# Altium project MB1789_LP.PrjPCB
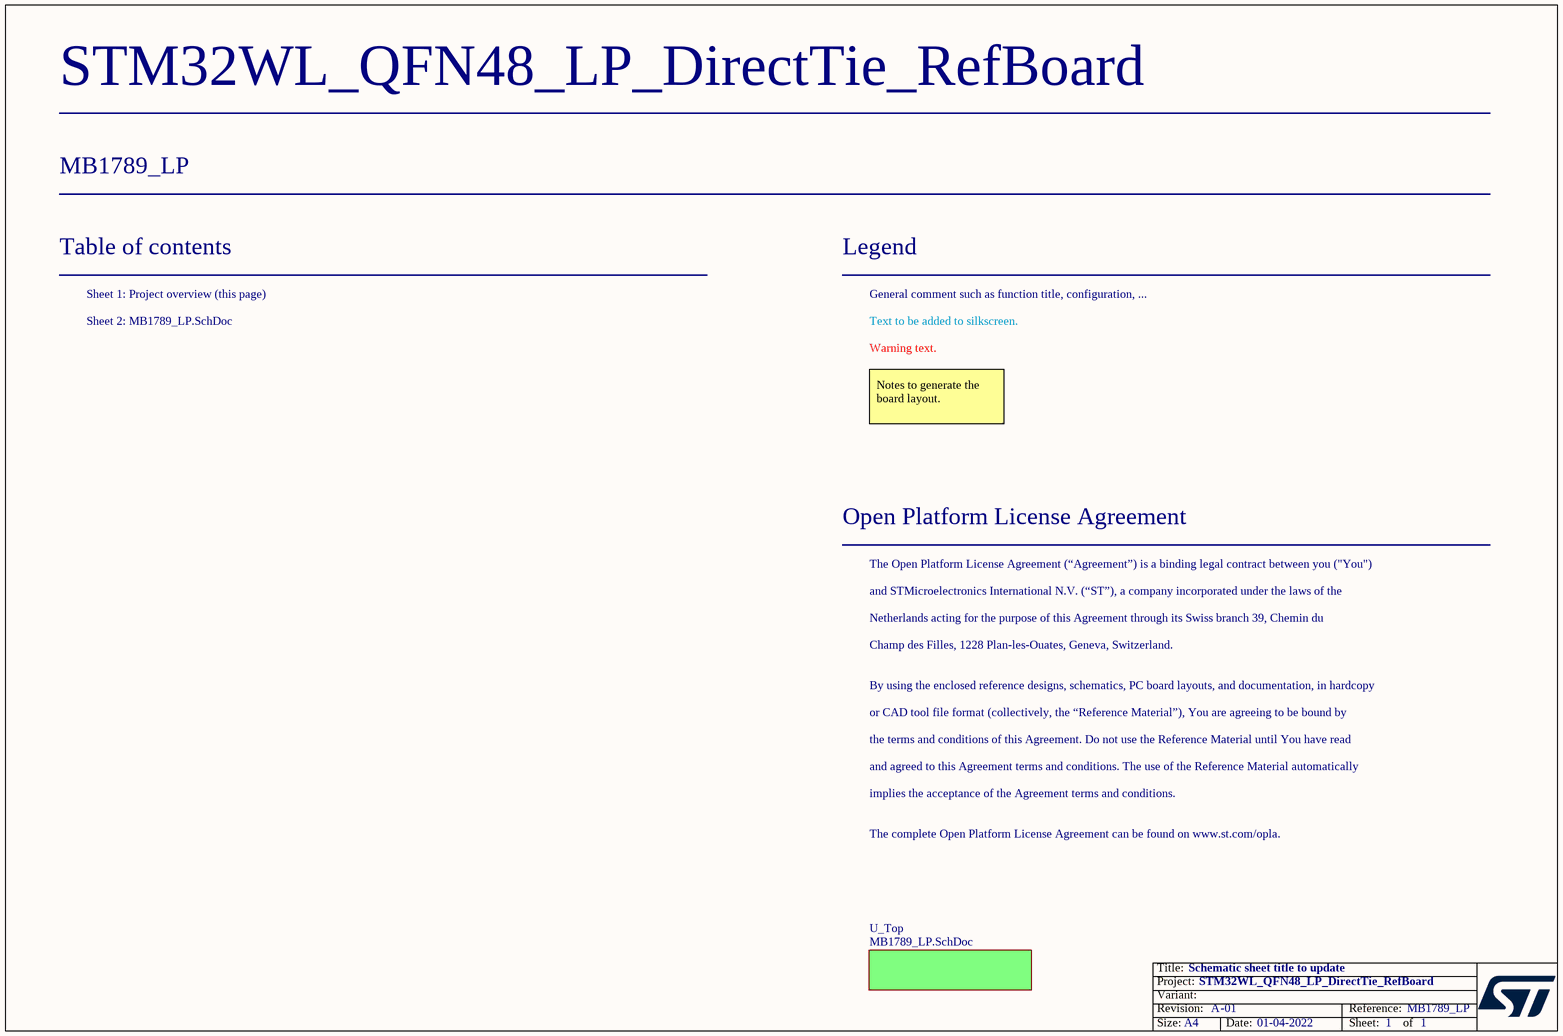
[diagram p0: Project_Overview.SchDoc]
Board_Reference: MB1789_LP; Board_PCB_Revision: A; Board_Name: STM32WL_QFN48_LP_DirectTie_RefBoard; Board_Document_Date: 01-04-2022; Board_Assembly_Revision: 01
2 sheets, 60 parts. Net scope: flat (ports and power ports of the same name join across sheets).
Board file: MB1789_LP.PcbDoc
Sheets:
  Project_Overview.SchDoc
    U_Top = MB1789_LP.SchDoc

## Sheet Project_Overview.SchDoc: Schematic sheet title to update
size A4; Date: Not used; ApprovedBy: Not used; CheckedBy: Not used; Author: Not used; CompanyName: STMicroelectronics; DrawnBy: Not used; Engineer: Not used; Organization: Not used; Address1: Not used; Address2: Not used; Address3: Not used; Address4: Not used; DocumentNumber: Not used; Revision: Not used; SheetNumber: 1; SheetTotal: 1

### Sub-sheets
U_Top = MB1789_LP.SchDoc: no entries

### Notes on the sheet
- Table of contents
- Sheet 1: Project overview (this page)
- Legend
- General comment such as function title, configuration, ...
- Sheet 2: MB1789_LP.SchDoc
- Text to be added to silkscreen.
- Warning text.
- Notes to generate the board layout.
- Open Platform License Agreement
- The Open Platform License Agreement (“Agreement”) is a binding legal contract between you ("You")
- and STMicroelectronics International N.V. (“ST”), a company incorporated under the laws of the
- Netherlands acting for the purpose of this Agreement through its Swiss branch 39, Chemin du
- Champ des Filles, 1228 Plan-les-Ouates, Geneva, Switzerland.
- By using the enclosed reference designs, schematics, PC board layouts, and documentation, in hardcopy
- or CAD tool file format (collectively, the “Reference Material”), You are agreeing to be bound by
- the terms and conditions of this Agreement. Do not use the Reference Material until You have read
- and agreed to this Agreement terms and conditions. The use of the Reference Material automatically
- implies the acceptance of the Agreement terms and conditions.
- The complete Open Platform License Agreement can be found on www.st.com/opla.

## Sheet MB1789_LP.SchDoc: Schematic sheet title to update
size A3; Date: Not used; ApprovedBy: Not used; CheckedBy: Not used; Author: Not used; CompanyName: STMicroelectronics; DrawnBy: Not used; Engineer: Not used; Organization: Not used; Address1: Not used; Address2: Not used; Address3: Not used; Address4: Not used; DocumentNumber: Not used; Revision: Not used; SheetNumber: 1; SheetTotal: 1
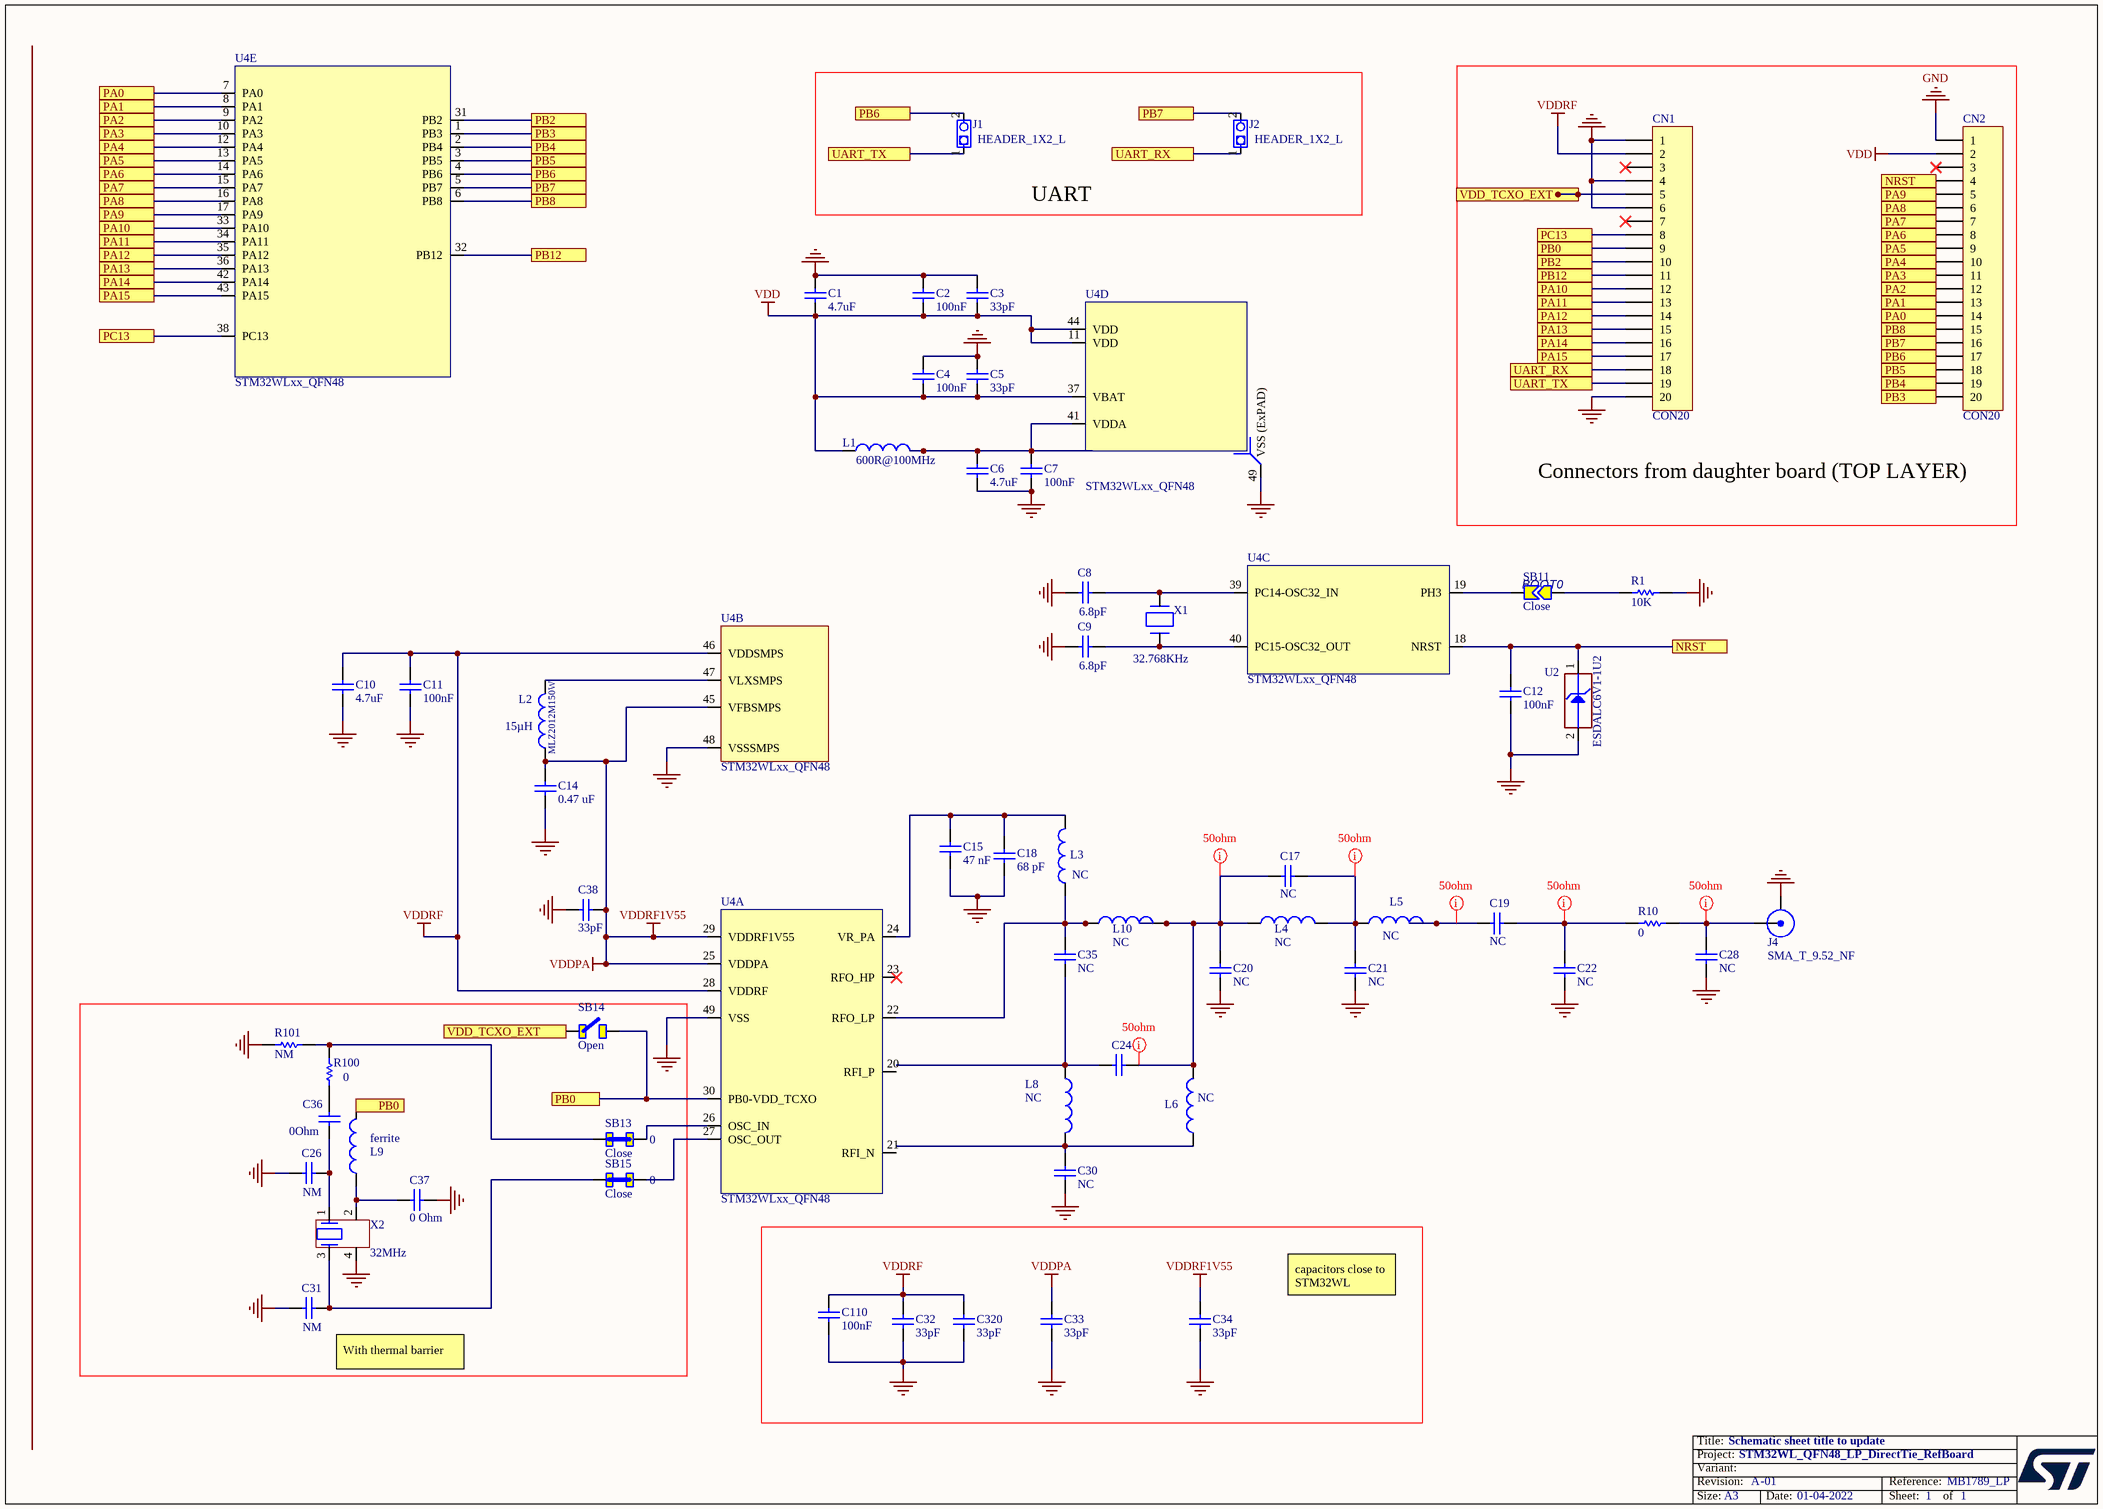
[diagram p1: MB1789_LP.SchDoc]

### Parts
C1  value 4.7uF  [CAPC1608X09N]
C2  value 100nF  [0402]
C3  value 33pF  [0201]
C4  value 100nF  [0402]
C5  value 33pF  [0201]
C6  value 4.7uF  [CAPC1608X09N]
C7  value 100nF  [0402]
C8  value 6.8pF  [0402]  (hidden comment: Capacitor)
C9  value 6.8pF  [0402]  (hidden comment: Capacitor)
C10  value 4.7uF  [CAPC1608X09N]
C11  value 100nF  [0402]
C12  value 100nF  [0402]
C14  value 0.47 uF  [CAPC1608X09N]
C15  value 47 nF  [0402]
C17  value NC  [0402]
C18  value 68 pF  [0402]
C19  value NC  [0402]
C20  value NC  [0402]
C21  value NC  [0402]
C22  value NC  [0402]
C24  (no value)  [0402]
C26  value NM  [0402]  (hidden comment: Capacitor)
C28  value NC  [0402]
C30  value NC  [0402]
C31  value NM  [0402]  (hidden comment: Capacitor)
C32  value 33pF  [0201]
C33  value 33pF  [0201]
C34  value 33pF  [0201]
C35  value NC  [0402]
C36  value 0Ohm  [0402]
C37  value 0 Ohm  [0402]
C38  value 33pF  [0201]
C110  value 100nF  [0402]
C320  value 33pF  [0201]
CN1  CON20
CN2  CON20
J1  HEADER_1X2_L  [CO_MOLEX_22-03-2021]
J2  HEADER_1X2_L  [CO_MOLEX_22-03-2021]
J4  SMA_T_9.52_NF  [CO_SAMTEC_SMA-J-P-ST-EMI]
L1  value 600R@100MHz  [INDC1608X95N]
L2  value 15µH  Manufacturer_Part_Number: MLZ2012M150W  [INDC2012X13N]
L3  value NC  [0402]
L4  value NC  [0402]
L5  value NC  [0402]
L6  value NC  [0402]
L8  value NC  [0402]
L9  ferrite  [IND_MURATA_LQW15A]
L10  value NC  [0402]
R1  value 10K  [RESC1608X05N]
R10  value 0  [R0402]  (hidden comment: Resistor)
R100  value 0  [R0402]  (hidden comment: Resistor)
R101  value NM  [R0402]  (hidden comment: Resistor)
SB11  Close  [GC_0402]
SB13  Close  value 0  [SB_0402]
SB14  Open  [SB_0402]
SB15  Close  value 0  [SB_0402]
U2  Manufacturer_Part_Number: ESDALC6V1-1U2  [DIOM0603X03N]
U4  STM32WLxx_QFN48  [STM32WLxx_QFN48]  (parts A,B,C,D,E of 5)
X1  value 32.768KHz  [OSC_NDK_NX2012SA]  (hidden comment: XTAL_2_PINS)
X2  value 32MHz  [OSC_NDK_NX2016SA]

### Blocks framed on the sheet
Connectors from daughter board (TOP LAYER): CN1 CN2
UART: J1 J2

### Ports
NRST, PA0, PA1, PA2, PA3, PA4, PA5, PA6, PA7, PA8, PA9, PA10, PA11, PA12, PA13, PA14, PA15, PB0, PB2, PB3, PB4, PB5, PB6, PB7, PB8, PB12, PC13, UART_RX, UART_TX, VDD_TCXO_EXT

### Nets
GND: C1.1 C2.1 C3.1 C4.1 C5.1 C6.2 C7.2 C8.2 C9.2 C10.2 C11.2 C12.2 C14.2 C15.2 C18.1 C20.2 C21.1 C22.1 C26.2 C28.2 C30.1 C31.2 C32.1 C33.1 C34.1 C37.1 C38.2 C110.2 C320.1 CN1.1 CN1.4 CN1.6 CN1.20 CN2.1 J4.2(Y) R1.1 R101.2 U2.2(GND) U4.48(VSSSMPS) U4.49(VSS_(ExPAD)) X2.4
VDD: C1.2 C2.2 C3.2 C4.2 C5.2 CN2.2 L1.1 U4.11(VDD) U4.37(VBAT) U4.44(VDD)
VDDPA: C14.1 C33.2 C34.2 C38.1 L2.1 U4.25(VDDPA) U4.29(VDDRF1V55) U4.45(VFBSMPS)  [also labelled VDDRF1V55]
VDDRF: C10.1 C11.1 C32.2 C110.1 C320.2 CN1.2 U4.28(VDDRF) U4.46(VDDSMPS)
NRST: C12.1 CN2.4 U2.1(IO1) U4.18(NRST) ; port NRST
PA0: CN2.14 U4.7(PA0) ; port PA0
PA1: CN2.13 U4.8(PA1) ; port PA1
PA2: CN2.12 U4.9(PA2) ; port PA2
PA3: CN2.11 U4.10(PA3) ; port PA3
PA4: CN2.10 U4.12(PA4) ; port PA4
PA5: CN2.9 U4.13(PA5) ; port PA5
PA6: CN2.8 U4.14(PA6) ; port PA6
PA7: CN2.7 U4.15(PA7) ; port PA7
PA8: CN2.6 U4.16(PA8) ; port PA8
PA9: CN2.5 U4.17(PA9) ; port PA9
PA10: CN1.12 U4.33(PA10) ; port PA10
PA11: CN1.13 U4.34(PA11) ; port PA11
PA12: CN1.14 U4.35(PA12) ; port PA12
PA13: CN1.15 U4.36(PA13) ; port PA13
PA14: CN1.16 U4.42(PA14) ; port PA14
PA15: CN1.17 U4.43(PA15) ; port PA15
PB0: CN1.9 L9.2 SB14.1 U4.30(PB0-VDD_TCXO) ; port PB0
PB2: CN1.10 U4.31(PB2) ; port PB2
PB3: CN2.20 U4.1(PB3) ; port PB3
PB4: CN2.19 U4.2(PB4) ; port PB4
PB5: CN2.18 U4.3(PB5) ; port PB5
PB6: CN2.17 J1.2 U4.4(PB6) ; port PB6
PB7: CN2.16 J2.2 U4.5(PB7) ; port PB7
PB8: CN2.15 U4.6(PB8) ; port PB8
PB12: CN1.11 U4.32(PB12) ; port PB12
PC13: CN1.8 U4.38(PC13) ; port PC13
UART_RX: CN1.18 J2.1 ; port UART_RX
UART_TX: CN1.19 J1.1 ; port UART_TX
VDD_TCXO_EXT: CN1.5 SB14.2 ; port VDD_TCXO_EXT
NetC6_1: C6.1 C7.1 L1.2 U4.41(VDDA)
NetC8_1: C8.1 U4.39(PC14-OSC32_IN) X1.2(X2)
NetC9_1: C9.1 U4.40(PC15-OSC32_OUT) X1.1(X1)
NetC15_1: C15.1 C18.2 L3.1 U4.24(VR_PA)
NetC17_1: C17.1 C20.1 C24.2 L4.1 L6.1 L10.2
NetC17_2: C17.2 C21.2 L4.2 L5.1
NetC19_1: C19.1 C22.2 R10.1
NetC19_2: C19.2 L5.2
NetC24_1: C24.1 C35.1 L8.1
NetC26_1: C26.1 C36.2 X2.1
NetC28_1: C28.1 J4.1(X) R10.2
NetC30_2: C30.2 L6.2 L8.2
NetC31_1: C31.1 SB15.2 X2.3
NetC35_2: C35.2 L3.2 L10.1 U4.22(RFO_LP)
NetC36_1: C36.1 R100.2
NetC37_2: C37.2 L9.1 X2.2
NetL2_2: L2.2 U4.47(VLXSMPS)
NetR1_2: R1.2 SB11.1
NetR100_1: R100.1 R101.1 SB13.2
NetSB11_2: SB11.2 U4.19(PH3)
NetSB13_1: SB13.1 U4.26(OSC_IN)
NetSB15_1: SB15.1 U4.27(OSC_OUT)

Not connected (* = marked no-connect by the designer): CN1 3* 7*; CN2 3*; U4 20(RFI_P) 21(RFI_N) 23(RFO_HP)*

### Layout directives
net class 50ohm: NetC17_1, NetC17_2, NetC19_1, NetC19_2, NetC28_1

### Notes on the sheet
- (near SB11) BOOT0
- capacitors close to STM32WL
- (near C31) With thermal barrier

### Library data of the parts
C1 C6 C10 = MCD-00009: Capacitor, MLCC, 4.7uF, 16V, X5R, 10%, 0603, T=0.8mm; Manufacturer_Part_Number: CC0603KRX5R7BB475; Manufacturer: YAGEO
C2 C4 C7 C11 C12 C110 = MCD-00102: Capacitor, MLCC, 100nF, 16V, X7R, 10%, 0402, T=0,5mm; Manufacturer_Part_Number: CC0402KRX7R7BB104; Manufacturer: YAGEO
C3 C5 = MCD-00102: Multilayer Ceramic Capacitors MLCC - SMD/SMT 0201 33pF 25volts C0G 5%; Manufacturer_Part_Number: GJM0335C1E330JB01D; Manufacturer: YAGEO
C8 C9 C26 C31 = MCD-00003: Capacitor, MLCC, 6.8pF, 50V, NPO, +-0.1pF, 0402, T=0.5mm; Manufacturer_Part_Number: GRM1555C1H6R8BA01; Manufacturer: MURATA
C14 = MCD-00009: Capacitor, MLCC, 4.7 uF, 16V, X5R, 10%, 0603, T=0.8mm; Manufacturer_Part_Number: CC0603KRX5R7BB474; Manufacturer: YAGEO
C15 = MCD-01123: Capacitor, MLCC,47nF, 16V, X7R, 10%, 0402, T=0.5mm; Manufacturer_Part_Number: GCM155R71E473KA55; Manufacturer: MURATA
C17 = MCD-01123
C18 = MCD-01123: Capacitor, MLCC,68pF, 50V, C0G, 1%, 0402, T=0.5mm; Manufacturer_Part_Number: GCM1555C1H680JA16; Manufacturer: MURATA
C19 = MCD-01123: Condensateurs céramique multicouches MLCC - CMS 33PF 50V 2% 0402
C20 = MCD-00102: N/C
C21 = MCD-00015: Condensateurs céramique multicouches MLCC - CMS 0402 3.3pF 50Volts C0G +/-0.05pF
C22 = MCD-01123: Condensateurs céramique multicouches MLCC - CMS 0402 2.7 pF 50Volts C0G +/-0.25pF
C24 = MCD-01123: Condensateurs céramique multicouches MLCC - CMS 0402 3.6pF 50Volts C0G +/-0.05pF; Manufacturer_Part_Number: GJM1555C1H3R6WB01D; Manufacturer: MURATA
C28 = Capacitor: Condensateurs céramique multicouches MLCC - CMS 0402 3.3pF 50Volts C0G +/-0.05pF
C30 = MCD-01123: Condensateurs céramique multicouches MLCC - CMS 0402 2.7pF 50Volts C0G +/-0.1pF
C32-C34 C320 = MCD-00277: Multilayer Ceramic Capacitors MLCC - SMD/SMT 0201 33pF 25volts C0G 5%; Manufacturer_Part_Number: GJM0335C1E330JB01D; Manufacturer: MURATA
C35 = MCD-01123: Condensateurs céramique multicouches MLCC - CMS 0402
C36 C37 = MCD-00277: Capacitor, MLCC, 33pF, 50V, NPO, 2%, 0402, T=0,5mm; Manufacturer_Part_Number: RCS04020000Z0ED; Manufacturer: Vishay / Dale
C38 = MCD-01123: Multilayer Ceramic Capacitors MLCC - SMD/SMT 0201 33pF 25volts C0G 5%; Manufacturer_Part_Number: GJM0335C1E330JB01D; Manufacturer: MURATA
CN1 CN2 = CON20: Connector
J4 = SMA_T_9.52_NF: SMA End Launch Jack 1.0 mm Board, 50 ohm; Manufacturer: COAX CONNECTORS LTD; Manufacturer_Part_Number: 30-462-D3-1.1mm
L1 = MCD-00047: SMD Chip ferrite bead, 600R@100MHz +/-25%, 350mA, 500mohm DC, 0603, T=0.8mm; Manufacturer_Part_Number: BK1608HS601-T; Manufacturer: Taiyo Yuden
L2 = MCD-01433: MLZ2012 Multilayer Shielded Inductor 15µH, ±5%; Manufacturer: TDK
L3 = MCD-01330: Inductor, 68nH, +-0.1nH, 140mA, 0402
L4 L10 = MCD-01330: Inductor, 8.2nH, +-0.2nH, 750mA, 0402
L5 = MCD-01330: Inductor, 8.7nH, +-0.1nH, 540mA, 0402
L6 = MCD-01330: Résistance 0 ohm
L8 = MCD-01330: Inductor, 11 nH, +-0.1nH, 270mA, 0402
L9 = MCD-01330: Inductor, 3.9nH, +-0.1nH, 750mA, 0402; Manufacturer: MURATA; Value: LQW15AN3N9B00#; Provided_By: SUBCO; Initial_Board_Reference: MB1402
R1 = MCD-00220: Resistor,10K,0603,1%,1/10W; Manufacturer_Part_Number: RC0603FR-0710KL; Manufacturer: YAGEO
R10 R100 R101 = MCD-00052: Resistor,0R,0402,5%,1/16W; Manufacturer_Part_Number: RC0402JR-070RL; Manufacturer: YAGEO; Provided_By: SUBCO; Initial_Board_Reference: MB1274
SB11 = Strap2: Solder Jumper - Close; Manufacturer: Vishay / Dale; Manufacturer_Part_Number: RCS04020000Z0ED
SB13 SB15 = SB_0Ohm: Solder Bridge 0R [0402] (Populated with 0 Ohm); Manufacturer: Vishay / Dale; Manufacturer_Part_Number: RCS04020000Z0ED
SB14 = SB_Open: Solder Bridge Open [0402] (Unpopulated)
U2 = MCD-00170: ESD protection 6V1; Manufacturer: STMICROELECTRONICS
U4 = STM32WLxx_QFN48: STM32WL ARM MCU Multiprotocol LPWAN 32-bit Arm Cortex-M4 MCUs LoRa (G)FSK-MSK BPSK; Manufacturer: STMicroelectronics; Manufacturer_Part_Number: STM32WLE5CC
X1 = MCD-01479: Crystal 32.768kHz, 6pF, -+20PPM, R=80K, SMD; Manufacturer_Part_Number: NX2012SA 32.768KHz EXS00A-MU00527; Manufacturer: NDK
X2 = MCD-01446: Crystal 32 MHz, 8pF, -+10 PPM, R=60Ω, SMD; Manufacturer_Part_Number: NX2016SA 32MHz EXS00A-CS06465; Manufacturer: NDK

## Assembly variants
LowBand_LowPower: not fitted C20 C24 C26 C28 C31 C32 C33 C34 C38 L6; alternate parts L10 -> MCD-00052
HighBand_LowPower: not fitted C17 C22 C24 C26 C28 C31 C38 L6; alternate parts L5 -> MCD-00052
